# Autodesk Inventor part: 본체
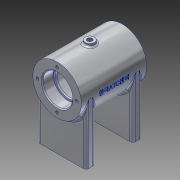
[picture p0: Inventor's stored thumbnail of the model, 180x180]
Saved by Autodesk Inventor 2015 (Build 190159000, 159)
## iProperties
Created: 2020-07
Part Number: 본체
Material: 알루미늄 6061
Document SubType Name: Modeling
Designer: LINEART-SSD.D4.16.04
Mass: 305.265 g
Surface Area: 357.573 cm^2
Volume: 113.061 cm^3
Density: 2.7 g/cm^3
Appearance: 알루미늄 - 평지
Author: LINEART-SSD.D4.16.04
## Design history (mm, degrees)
sketch "스케치1"
  geometry: C1 r 26 at (0, 0); 1 further point
  constraints: 1 centre point, 1 coincident
  dimensions: "d0" = 52 diameter of C1
extrude "돌출1" new body sketch "스케치1" stored distance "d1" = 70; taper "d2" = 0 deg
hole "구멍1" diameter "d5" = 28; stored, may be unused: countersink angle "d9" = 90 deg, drill point angle "d11" = 118 deg; dims "d3" = 10, "d4" = 10, "d6" = 6, "d7" = 32, "d8" = 12, "d10" = 8
sketch "스케치2"
  geometry: C1 r 21 at (0, 0); 1 further point
  constraints: 1 centre point, 1 coincident
  dimensions: "d12" = 42 diameter of C1
extrude "돌출2" cut sketch "스케치2" stored distance "d13" = 42; taper "d14" = 0 deg
fillet "모깎기1" dims "d15" = 3
fillet "모깎기2" dims "d16" = 0.3
chamfer "모따기1" distance "d17" = 1; stored, may be unused: second distance "d18" = 2, angle "d19" = 45 deg
node "작업 평면2"
  node "작업 평면1"
sketch "스케치3"
  geometry: C1 r 5 at (0, 0); 1 further point
  constraints: 1 centre point, 1 coincident
  dimensions: "d21" = 10 diameter of C1
extrude "돌출3" join sketch "스케치3" stored distance "d22" = 42; taper "d23" = 0 deg
sketch "스케치4"
  geometry: L1 (0, 0)-(9.919, -27.251); L2 (0, 0)-(29, 0); L3 (9.919, -27.251)-(15.557, -25.199); L4 (15.557, -25.199)-(14.048, -21.054); L5 (14.048, -21.054)-(8.41, -23.106)
  constraints: 10 end point, 2 perpendicular, 1 equal length, 1 horizontal, 1 point on line
  dimensions: "d24" = 29 distance of L1.start L1.end; "d25" = 70 deg angle of L1 L2; "d27" = 6 distance of L1.end L3.end; "d28" = 4.41104 distance between parallel lines of L3 L5
revolve "회전1" sketch "스케치4" stored, may be unused: angle "d29" = 90 deg
hole "구멍2" diameter "d32" = 5.188; stored, may be unused: countersink angle "d36" = 90 deg, drill point angle "d38" = 118 deg; dims "d30" = 10, "d31" = 10, "d33" = 12, "d34" = 32, "d35" = 12, "d37" = 16
hole "구멍3" diameter "d41" = 5.188; stored, may be unused: countersink angle "d45" = 90 deg, drill point angle "d47" = 118 deg; dims "d39" = 10, "d40" = 10, "d42" = 12, "d43" = 32, "d44" = 12, "d46" = 16
fillet "모깎기3" dims "d48" = 2
node "작업 평면3"
sketch "스케치5"
  geometry: L1 (-26, 0)-(-26, -64); L2 (-26, -64)-(26, -64); L3 (26, -64)-(26, 0); C1 r 17 at (0, 0) reference; A1 r 26 centre (0, 0) between (-26, 0) and (26, 0) reference; A2 r 26 centre (0, 0) between (-26, 0) and (26, 0) reference; A3 r 26 centre (0, 0) between (-26, 0) and (26, 0); 1 further point
  constraints: 6 end point, 6 point on circle, 1 centre point, 1 concentric, 1 perpendicular, 1 tangent, 1 vertical
  dimensions: "d50" = 64 distance of L1.start L1.end; "d51" = 52 distance of L1.end L2.end; "d52" = 63.99954 distance of L2.end L3.end
extrude "돌출4" join sketch "스케치5" distance "d53" = 10; taper "d54" = 0 deg
fillet "모깎기4" dims "d55" = 3
fillet "모깎기5" dims "d56" = 3
sketch "스케치6"
  geometry: C1 r 26 at (0, 0) reference; C2 r 17 at (0, 0) reference; 2 further points
  constraints: 1 vertical alignment
  dimensions: "d57" = 21 distance of point (0, 21) point (0, 0)
hole "구멍4" sketch "스케치6" at (0, 21) diameter "d58" = 3.242; stored, may be unused: countersink angle "d62" = 90 deg, drill point angle "d64" = 118 deg; dims "d59" = 8, "d60" = 32, "d61" = 12, "d63" = 10
sketch "스케치7"
  geometry: L1 (0, 0)-(46, 0) reference; L2 (49, 3)-(49, 7) reference; L3 (0, 10)-(46, 10) reference; L4 (-3, 3)-(-3, 7) reference; L5 (0, -40)-(46, -40) reference; L6 (-3, -43)-(-3, -47) reference; L7 (0, -50)-(46, -50) reference; L8 (49, -43)-(49, -47) reference; A1 r 3 centre (0, 3) between (-3, 3) and (0, 0) reference; A2 r 3 centre (46, 3) between (46, 0) and (49, 3) reference; A3 r 3 centre (46, 7) between (49, 7) and (46, 10) reference; A4 r 3 centre (0, 7) between (0, 10) and (-3, 7) reference; A5 r 3 centre (46, -43) between (49, -43) and (46, -40) reference; A6 r 3 centre (0, -43) between (0, -40) and (-3, -43) reference; A7 r 3 centre (0, -47) between (-3, -47) and (0, -50) reference; A8 r 3 centre (46, -47) between (46, -50) and (49, -47) reference; 5 further points
  constraints: 2 horizontal alignment, 2 vertical alignment
  dimensions: "d68" = 20 horizontal distance of point (43, 5) point (23, -20); "d69" = 5 distance from line of point (43, 5) L3; "d70" = 40 distance of point (3, 5) point (43, 5); "d71" = 25 vertical distance of point (43, -45) point (23, -20)
hole "구멍5" sketch "스케치7" at (43, 5), (3, 5), (43, -45), (3, -45) diameter "d72" = 4.134; stored, may be unused: countersink angle "d76" = 90 deg, drill point angle "d78" = 118 deg; dims "d73" = 8, "d74" = 32, "d75" = 12, "d77" = 10
node "작업 평면4"
sketch "스케치8"
  geometry: L1 (-26, -35)-(26, -35) reference; L2 (-26, -35)-(-26, 35) reference; 2 further points
  constraints: 1 other
  dimensions: "d79" = 35 distance from line of point (0, 0) L1; "d80" = 26 distance from line of point (0, 0) L2
feature "엠보싱1" sketch "스케치8" dims "d81" = 0.5, "d82" = 0
node "솔리드1"
mirror "대칭1"
mirror "대칭2"
pattern_circular "원형 패턴1" dims angle "d66" = 360 deg
mirror "대칭3"
node "투영된 루프1"
node "투영된 루프2"
node "투영된 루프3"
node "투영된 루프4"
other parameters: "d20" = 3
